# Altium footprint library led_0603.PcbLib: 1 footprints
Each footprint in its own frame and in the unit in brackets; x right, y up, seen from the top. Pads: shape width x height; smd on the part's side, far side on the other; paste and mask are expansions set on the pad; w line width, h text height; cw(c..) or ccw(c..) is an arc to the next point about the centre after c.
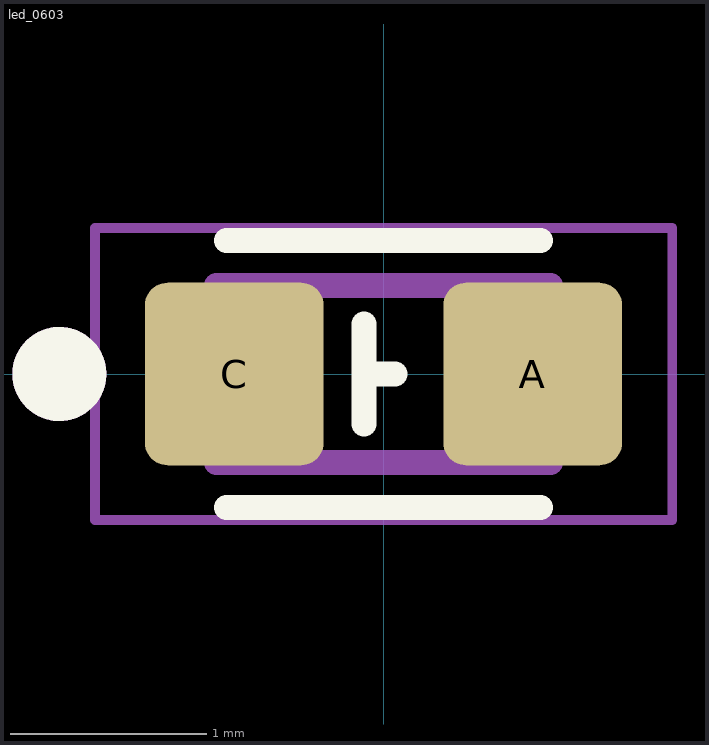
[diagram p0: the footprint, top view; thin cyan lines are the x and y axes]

## led_0603 [mm]
pads (2):
  rrect25% 0.91x0.93 smd: A(0.76,0) C(-0.76,0)
Top Overlay:
  circle w0.24: c-1.651,0 r0.12
  lines w0.127: -0.8,-0.68 0.8,-0.68 ; -0.8,0.68 0.8,0.68 ; -0.1,-0.254 -0.1,0.254 ; -0.1,0 0.059,0
Mechanical 13:
  circle w0.24: c-1.651,0 r0.12
  lines w0.127: -0.85,-0.45 0.85,-0.45 0.85,0.45 -0.85,0.45 -0.85,-0.45
Mechanical 15:
  lines w0.05: -1.47,-0.744 1.47,-0.744 1.47,0.744 -1.47,0.744 -1.47,-0.744
3D body "led_0603.step": height 0.65, standoff 0, extent -0.801,-0.399 0.799,0.401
